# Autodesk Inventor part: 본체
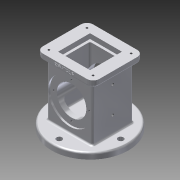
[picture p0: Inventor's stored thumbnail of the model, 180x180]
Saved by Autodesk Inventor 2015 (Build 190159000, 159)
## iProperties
Created: 2018-10
Part Number: 본체
Material: 알루미늄 6061
Document SubType Name: Modeling
Designer: cad1-7
Density: 2.7 g/cm^3
Appearance: 알루미늄 - 평지
Mass: 983.358 g
Surface Area: 757.555 cm^2
Volume: 364.207 cm^3
Author: cad1-7
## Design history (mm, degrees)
sketch "스케치2"
  geometry: L1 (-37, 33)-(37, 33); L2 (37, 33)-(37, -33); L3 (37, -33)-(-37, -33); L4 (-37, -33)-(-37, 33); L5 (-37, 33)-(37, -33); L6 (37, 33)-(-37, -33); 1 further point
  constraints: 12 end point, 2 midpoint, 2 parallel, 1 horizontal, 1 perpendicular
  dimensions: "d1" = 74 distance of L2.end L3.end; "d2" = 66 distance of L1.end L2.end
extrude "돌출1" new body sketch "스케치2" stored distance "d3" = 88; taper "d4" = 0 deg
sketch "스케치3"
  geometry: C1 r 62.5 at (0, 0); 1 further point
  constraints: 1 centre point, 1 coincident
  dimensions: "d5" = 125 diameter of C1
extrude "돌출2" join sketch "스케치3" distance "d6" = 10; taper "d7" = 0 deg
sketch "스케치4"
  geometry: L1 (46, -41)-(-46, -41); L2 (-46, -41)-(-46, 41); L3 (-46, 41)-(46, 41); L4 (46, 41)-(46, -41); L5 (46, -41)-(-46, 41); L6 (-46, -41)-(46, 41); 1 further point
  constraints: 12 end point, 2 midpoint, 2 parallel, 1 horizontal, 1 perpendicular
  dimensions: "d8" = 92 distance of L2.end L3.end; "d9" = 82 distance of L1.end L2.end
extrude "돌출3" join sketch "스케치4" distance "d10" = 10; taper "d11" = 0 deg
sketch "스케치5"
  geometry: C1 r 28 at (0, 0); 1 further point
  constraints: 1 centre point, 1 coincident
  dimensions: "d12" = 56 diameter of C1
extrude "돌출4" cut sketch "스케치5" distance "d13" = 18; taper "d14" = -10 deg
sketch "스케치6"
  geometry: L1 (0, 0)-(-50, 0); 1 further point
  constraints: 2 end point, 1 coincident, 1 horizontal
  dimensions: "d15" = 50 distance of L1.start L1.end
hole "구멍1" sketch "스케치6" at (-50, 0) diameter "d16" = 9; stored, may be unused: countersink angle "d20" = 90 deg, drill point angle "d22" = 118 deg; dims "d17" = 6, "d18" = 4, "d19" = 2, "d21" = 8
sketch "스케치7"
  geometry: L1 (26, 26)-(-26, 26); L2 (-26, 26)-(-26, -26); L3 (-26, -26)-(26, -26); L4 (26, -26)-(26, 26); L5 (26, 26)-(-26, -26); L6 (-26, 26)-(26, -26); 1 further point
  constraints: 12 end point, 2 midpoint, 2 parallel, 1 horizontal, 1 perpendicular
  dimensions: "d26" = 52 distance of L3.end L2.end; "d27" = 52 distance of L2.end L1.end
extrude "돌출5" cut sketch "스케치7" distance "d28" = 8; taper "d29" = 0 deg
sketch "스케치9"
  geometry: L1 (-25.5, -10)-(99.5, -10) reference; C1 r 35 at (37, 44); 1 further point
  constraints: 1 centre point, 1 coincident
  dimensions: "d32" = 70 diameter of C1; "d33" = 54 distance from line of C1.centre L1
extrude "돌출6" cut sketch "스케치9" distance "d34" = 3; taper "d35" = 0 deg
sketch "스케치10"
  geometry: C1 r 24 at (0, 0); 1 further point
  constraints: 1 centre point, 1 coincident
  dimensions: "d36" = 48 diameter of C1
extrude "돌출7" cut sketch "스케치10" stored distance "d37" = 3; taper "d38" = 0 deg
sketch "스케치11"
  geometry: L1 (-22, 22)-(22, 22); L2 (22, 22)-(22, -22); L3 (22, -22)-(-22, -22); L4 (-22, -22)-(-22, 22); L5 (-22, 22)-(22, -22); L6 (22, 22)-(-22, -22); 1 further point
  constraints: 12 end point, 2 midpoint, 2 parallel, 1 horizontal, 1 perpendicular
  dimensions: "d39" = 44 distance of L2.end L3.end; "d40" = 44 distance of L1.end L2.end
extrude "돌출8" cut sketch "스케치11" distance "d41" = 74; taper "d42" = 0 deg
fillet "모깎기1" dims "d43" = 10, "d48" = 3
fillet "모깎기2" dims "d57" = 3
sketch "스케치12"
  geometry: L1 (-10, 10)-(-10, 0) reference; L2 (0, 10)-(72, 10) reference; 2 further points
  constraints: 1 other
  dimensions: "d58" = 46 distance from line of L1 point (36, 6); "d59" = 4 distance from line of L2 point (36, 6)
feature "엠보싱1" sketch "스케치12" dims "d1" = 74, "d2" = 66, "d60" = 0.5, "d61" = 0
sketch "스케치15"
  geometry: A1 r 10 centre (-36, 31) between (-36, 41) and (-46, 31) reference; A2 r 10 centre (36, 31) between (46, 31) and (36, 41) reference; A3 r 10 centre (36, -31) between (36, -41) and (46, -31) reference; A4 r 10 centre (-36, -31) between (-46, -31) and (-36, -41) reference; 1 further point
hole "구멍4" sketch "스케치15" at (-36, 31), (-36, -31), (36, -31), (36, 31) diameter "d79" = 3.242; stored, may be unused: countersink angle "d83" = 90 deg, drill point angle "d85" = 118 deg; dims "d80" = 4, "d81" = 4, "d82" = 2, "d84" = 6
sketch "스케치16"
  geometry: L1 (0, 0)-(0, 29); 1 further point
  constraints: 2 end point, 1 coincident, 1 vertical
  dimensions: "d86" = 29 distance of L1.start L1.end
hole "구멍5" sketch "스케치16" at (0, 29) diameter "d87" = 3.242; stored, may be unused: countersink angle "d91" = 90 deg, drill point angle "d93" = 118 deg; dims "d88" = 4, "d89" = 4, "d90" = 2, "d92" = 6
sketch "스케치17"
  geometry: L1 (-92.5, -10)-(32.5, -10) reference; 3 further points
  constraints: 2 vertical alignment
  dimensions: "d97" = 43 distance of point (-30, 27) point (-30, 70); "d98" = 37 distance from line of L1 point (-30, 27)
hole "구멍6" sketch "스케치17" at (-30, 70), (-30, 27) diameter "d99" = 4.134; stored, may be unused: countersink angle "d103" = 90 deg, drill point angle "d105" = 0 deg; dims "d100" = 14.99, "d101" = 4, "d102" = 2, "d104" = 19.19
fillet "모깎기3" dims "d114" = 3
node "솔리드1"
pattern_circular "원형 패턴1" dims angle "d24" = 360 deg
mirror "대칭1"
pattern_circular "원형 패턴2" dims angle "d95" = 360 deg
mirror "대칭2"
other parameters: "d44" = 0.5, "d45" = 2, "d46" = 0, "d49" = 0.5, "d50" = 2, "d51" = 0, "d53" = 0.5, "d54" = 2, "d55" = -220.25, "d106" = 0.5, "d107" = 2, "d108" = 0, "d110" = 0.5, "d111" = 2
